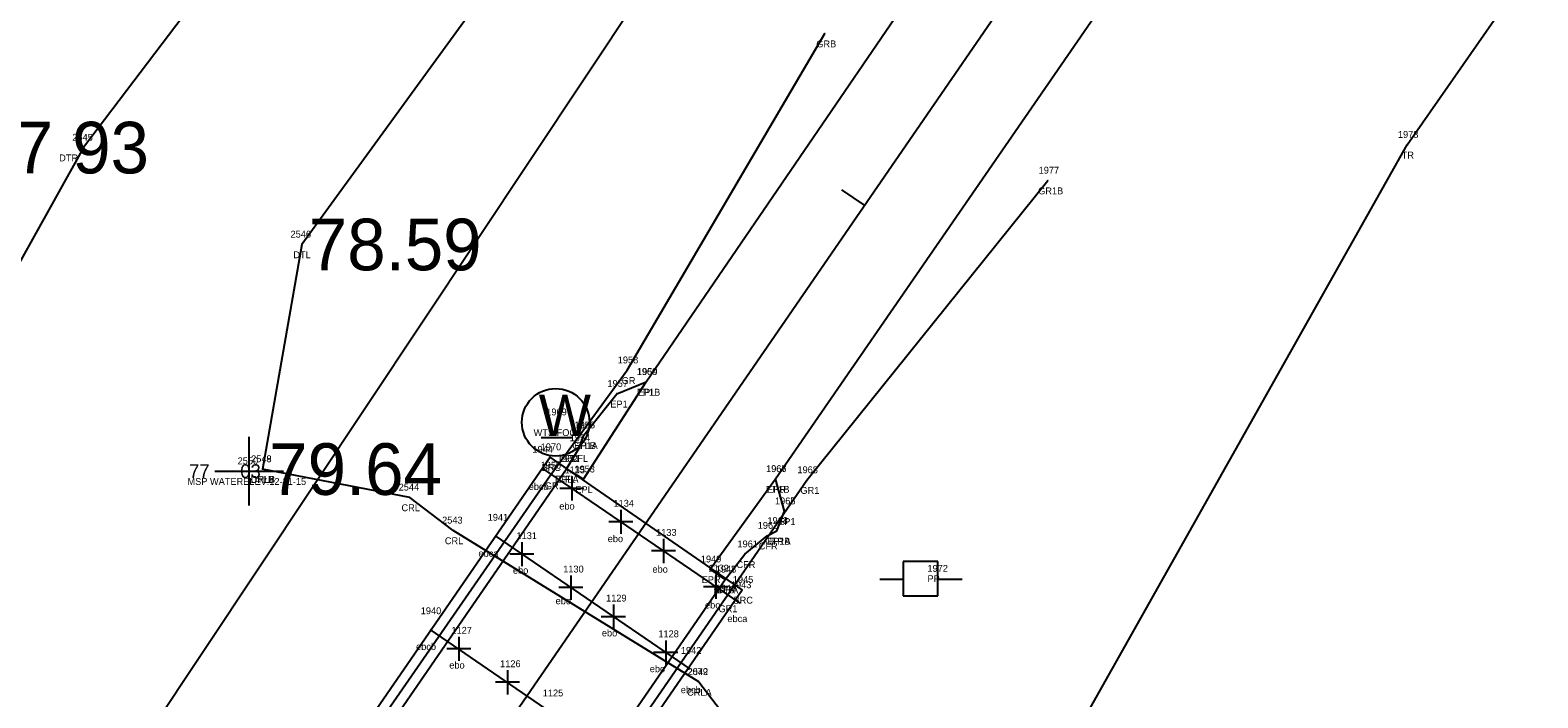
# Model space of a CAD drawing. Extents: x 2266664 to 2272542, y 716533 to 724777.
# Drawn here: x 2269953.4 to 2270172.5, y 721369.4 to 721466.4 of the extents above; entities that cross this region are included whole.
import ezdxf

# ---------------------------------------------------------------- set-up
doc = ezdxf.new("R2010")
doc.units = 0
for name, color, linetype in [('RD_EX_Bridge', 7, 'Continuous'), ('RD_EX_Bridge_txCode', 7, 'Continuous'), ('RD_EX_Conc', 7, 'Continuous'), ('RD_EX_Conc_txCode', 7, 'Continuous'), ('RD_EX_DR_Inlet_txCode', 7, 'Continuous'), ('RD_EX_GuardRail', 7, 'Continuous'), ('RD_EX_GuardRail_txCode', 7, 'Continuous'), ('RD_EX_H2O', 7, 'Continuous'), ('RD_EX_H2O_txCode', 7, 'Continuous'), ('RD_EX_Misc', 7, 'Continuous'), ('RD_EX_Misc_txCode', 7, 'Continuous'), ('RD_EX_Road', 7, 'Continuous'), ('RD_EX_Road_txCode', 7, 'Continuous'), ('RD_EX_UT', 7, 'Continuous'), ('RD_EX_UT_txCode', 7, 'Continuous'), ('RD_EX_VEG', 7, 'Continuous'), ('RD_EX_VEG_txCode', 7, 'Continuous'), ('RD_HC_Cl', 7, 'Continuous'), ('RD_HC_Data_Tic', 7, 'Continuous'), ('RD_SMD_Locator', 7, 'Continuous')]:
    doc.layers.add(name, color=color, linetype=linetype)

msp = doc.modelspace()

# ---------------------------------------------------------------- linework, layer by layer
at = {"layer": 'RD_EX_Bridge'}
msp.add_lwpolyline([(2269960.85, 721305.41), (2269988.95, 721286.47), (2270056.9, 721385.08), (2270029.02, 721404.36), (2269960.85, 721305.41)], dxfattribs=at)
at = {"layer": 'RD_EX_Conc'}
for points in [[(2269963.38, 721303.82), (2269997.07, 721352.85), (2270031.4, 721402.66), (2270033.2, 721405.68), (2270033.91, 721407.54)], [(2269983.54, 721282.33), (2269984.17, 721283.64), (2269986.54, 721288.04), (2270020.48, 721337.28), (2270054.42, 721386.58), (2270057.31, 721390.25), (2270060.54, 721392.95), (2270061.95, 721393.64)]]:
    msp.add_lwpolyline(points, dxfattribs=at)
at = {"layer": 'RD_EX_GuardRail'}
for points in [[(2269870.57, 721186.54), (2269949.59, 721286.31), (2269962.16, 721304.4), (2269963.29, 721306.38), (2269995.7, 721353.55), (2270029.01, 721401.69), (2270040.18, 721416.99), (2270068.93, 721465.92)], [(2269974.73, 721236.37), (2269968.22, 721240.45), (2269964.64, 721248.3), (2269966.87, 721257.97), (2269988.88, 721288.81), (2270021.75, 721336.4), (2270054.42, 721383.83), (2270066.31, 721401.03), (2270101.34, 721444.56)]]:
    msp.add_lwpolyline(points, dxfattribs=at)
at = {"layer": 'RD_EX_H2O'}
for points in [[(2271033.41, 722941.96), (2271017.26, 722923.37), (2271000.84, 722915.61), (2270984.69, 722924.7), (2270953.1, 722884.21), (2270916.86, 722756.99), (2270859.77, 722671.98), (2270798.36, 722591.12), (2270738.02, 722501.89), (2270682.59, 722424.89), (2270629.35, 722346.56), (2270572.53, 722262.27), (2270515.87, 722180.88), (2270459.66, 722106.47), (2270403.98, 722020.3), (2270343.58, 721932.89), (2270284.34, 721846.17), (2270230.48, 721766.75), (2270175.19, 721692.18), (2270115.51, 721607.69), (2270056.41, 721522.72), (2269992.94, 721435.27), (2269987.18, 721402.63)], [(2270599.29, 722364.14), (2270544.36, 722283.47), (2270486.41, 722202.72), (2270437.65, 722128.66), (2270381.61, 722049.14), (2270312.65, 721946.45), (2270267.02, 721881.66), (2270199.49, 721783.94), (2270145.55, 721706.24), (2270092.32, 721634.06), (2270029.51, 721539.41), (2269961.2, 721449.35), (2269937.69, 721407.23), (2269942.44, 721394.39), (2269941.06, 721353.93), (2269922.62, 721344.96)], [(2270050.62, 721371.69), (2270014.93, 721393.71), (2270008.62, 721398.51), (2269987.18, 721402.63)], [(2270050.62, 721371.69), (2270058.64, 721361.22), (2270067.88, 721340.59), (2270071.72, 721335.84), (2270077.18, 721322.68), (2270100.02, 721315.03), (2270109.33, 721309.47), (2270127.84, 721291.83), (2270185.1, 721310.38), (2270243.87, 721304.44), (2270281.75, 721346.08), (2270379.45, 721379), (2270436.63, 721386.23), (2270462.17, 721399.02)]]:
    msp.add_lwpolyline(points, dxfattribs=at)
at = {"layer": 'RD_EX_Misc'}
for p, q in [((2269985.26, 721397.33), (2269985.26, 721407.33)), ((2269980.26, 721402.33), (2269990.26, 721402.33)), ((2270056.61, 721383.12), (2270027.78, 721402.8)), ((2270032.17, 721401.56), (2270032.17, 721398.06)), ((2270033.92, 721399.81), (2270030.42, 721399.81)), ((2270039.27, 721396.71), (2270039.27, 721393.21)), ((2270041.02, 721394.96), (2270037.52, 721394.96)), ((2270020.99, 721392.92), (2270049.34, 721373.57)), ((2270024.89, 721392), (2270024.89, 721388.5)), ((2270045.46, 721392.48), (2270045.46, 721388.98)), ((2270026.64, 721390.25), (2270023.14, 721390.25)), ((2270047.21, 721390.73), (2270043.71, 721390.73)), ((2270032, 721387.15), (2270032, 721383.65)), ((2270053.06, 721387.29), (2270053.06, 721383.79)), ((2270033.75, 721385.4), (2270030.25, 721385.4)), ((2270054.81, 721385.54), (2270051.31, 721385.54)), ((2270038.19, 721382.93), (2270038.19, 721379.43)), ((2270039.94, 721381.18), (2270036.44, 721381.18)), ((2270040.13, 721359.75), (2270011.59, 721379.34)), ((2270015.72, 721378.25), (2270015.72, 721374.75)), ((2270017.47, 721376.5), (2270013.97, 721376.5)), ((2270047.54, 721375.99), (2270044.04, 721375.99)), ((2270045.79, 721377.74), (2270045.79, 721374.24)), ((2270024.56, 721371.64), (2270021.06, 721371.64)), ((2270022.81, 721373.39), (2270022.81, 721369.89))]:
    msp.add_line(p, q, dxfattribs=at)
at = {"layer": 'RD_EX_Road'}
for points in [[(2270031.4, 721402.66), (2270033.87, 721401.14), (2270042.98, 721415.3), (2270092.2, 721487.45), (2270150.09, 721571.44), (2270208.05, 721655.62), (2270267.22, 721742.06), (2270325.8, 721826.88), (2270384.21, 721912), (2270439.48, 721992.72), (2270498.7, 722078.55)], [(2270054.42, 721386.58), (2270052.25, 721388.06), (2270061.76, 721401.19), (2270112.33, 721474.56), (2270169.63, 721557.76), (2270228.06, 721642.37), (2270287.52, 721728.67), (2270345.88, 721813.8), (2270404.16, 721898.12), (2270459.42, 721978.97), (2270518.64, 722064.54)], [(2270033.91, 721407.54), (2270038.67, 721413.57), (2270042.98, 721415.3)], [(2270061.95, 721393.64), (2270063.05, 721396.5), (2270061.76, 721401.19)]]:
    msp.add_lwpolyline(points, dxfattribs=at)
at = {"layer": 'RD_EX_UT'}
for p, q in [((2270027.68, 721407.22), (2270032.31, 721407.22)), ((2270085.32, 721389.21), (2270080.32, 721389.21)), ((2270080.32, 721389.21), (2270080.32, 721384.21)), ((2270085.32, 721384.21), (2270085.32, 721389.21)), ((2270076.89, 721386.65), (2270080.36, 721386.65)), ((2270085.25, 721386.65), (2270088.89, 721386.65)), ((2270080.32, 721384.21), (2270085.32, 721384.21))]:
    msp.add_line(p, q, dxfattribs=at)
msp.add_circle((2270029.81, 721409.43), 4.91, dxfattribs=at)
at = {"layer": 'RD_EX_VEG'}
for points in [[(2268819.78, 719716.8), (2268871.54, 719776.21), (2269193.85, 720224.65), (2269408.57, 720538.5), (2269589.67, 720791.77), (2270047.56, 721479.8), (2270363.13, 721951.09), (2270746.65, 722498.38), (2270919.94, 722752.82), (2271017.26, 722923.37)], [(2269982.26, 721145.34), (2270153.55, 721449.76), (2270271.14, 721618.55), (2270388.14, 721782.77), (2270502.37, 721950.48), (2270556.28, 722038.41)]]:
    msp.add_lwpolyline(points, dxfattribs=at)
at = {"layer": 'RD_HC_Cl'}
msp.add_line((2267342.91, 717471.2), (2272360.46, 724762.59), dxfattribs=at)
at = {"layer": 'RD_HC_Data_Tic'}
msp.add_line((2270074.69, 721440.97), (2270071.4, 721443.23), dxfattribs=at)
at = {"layer": 'RD_SMD_Locator'}
for centre in [(2270068.93, 721465.92), (2269961.2, 721449.35), (2270153.55, 721449.76), (2270101.34, 721444.56), (2269992.94, 721435.27), (2270040.18, 721416.99), (2270038.67, 721413.57), (2270042.98, 721415.3), (2270042.98, 721415.3), (2270033.91, 721407.54), (2270033.91, 721407.54), (2270033.2, 721405.68), (2269987.18, 721402.63), (2269987.18, 721402.63), (2270029.02, 721404.36), (2270031.4, 721402.66), (2270031.4, 721402.66), (2270029.01, 721401.69), (2270033.87, 721401.14), (2270061.76, 721401.19), (2270061.76, 721401.19), (2270066.31, 721401.03), (2270008.62, 721398.51), (2270063.05, 721396.5), (2270014.93, 721393.71), (2270061.95, 721393.64), (2270061.95, 721393.64), (2270060.54, 721392.95), (2270057.31, 721390.25), (2270052.25, 721388.06), (2270054.42, 721386.58), (2270054.42, 721386.58), (2270056.9, 721385.08), (2270054.42, 721383.83), (2270050.62, 721371.69), (2270050.62, 721371.69)]:
    msp.add_circle(centre, 0.001, dxfattribs=at)

# ---------------------------------------------------------------- texts
at = {"layer": 'RD_EX_Bridge_txCode'}
for s, p in [('1970', (2270027.63, 721405.36)), ('BRC', (2270027.76, 721402.36)), ('1945', (2270055.55, 721386.08)), ('BRC', (2270055.65, 721383.08))]:
    msp.add_text(s, height=1, dxfattribs=at).set_placement(p)
at = {"layer": 'RD_EX_Conc_txCode'}
for s, p in [('1955', (2270032.56, 721408.54)), ('1954', (2270031.85, 721406.68)), ('1951', (2270030.34, 721403.66)), ('CFL', (2270031.99, 721403.68)), ('CFLB', (2270032.23, 721405.54)), ('CFL', (2270030.2, 721400.66)), ('1963', (2270060.58, 721394.64)), ('1962', (2270059.17, 721393.95)), ('1961', (2270056.22, 721391.25)), ('CFR', (2270059.32, 721390.95)), ('CFRB', (2270060.25, 721391.64)), ('CFR', (2270056.08, 721388.25)), ('1947', (2270053.07, 721387.58)), ('CFR', (2270053.19, 721384.58))]:
    msp.add_text(s, height=1, dxfattribs=at).set_placement(p)
at = {"layer": 'RD_EX_DR_Inlet_txCode'}
for s, p in [('77 93', (2269945.61, 721445.6)), ('78.59', (2269993.94, 721431.52)), ('79.64', (2269988.18, 721398.88))]:
    msp.add_text(s, height=7.5, dxfattribs=at).set_placement(p)
at = {"layer": 'RD_EX_GuardRail_txCode'}
for s, p in [('GRB', (2270067.68, 721463.92)), ('1977', (2270099.99, 721445.56)), ('GR1B', (2270099.92, 721442.56)), ('1958', (2270038.83, 721417.99)), ('GR', (2270039.4, 721414.99)), ('1950', (2270027.62, 721402.69)), ('1968', (2270064.94, 721402.03)), ('GR', (2270028.23, 721399.69)), ('GR1', (2270065.37, 721399.03)), ('1946', (2270053.05, 721384.83)), ('GR1', (2270053.47, 721381.83))]:
    msp.add_text(s, height=1, dxfattribs=at).set_placement(p)
at = {"layer": 'RD_EX_H2O_txCode'}
for s, p in [('2545', (2269959.57, 721450.35)), ('DTR', (2269957.66, 721447.35)), ('2546', (2269991.28, 721436.27)), ('DTL', (2269991.69, 721433.27)), ('2548', (2269985.55, 721403.63)), ('2549', (2269985.55, 721403.63)), ('CRLB', (2269985.48, 721400.63)), ('DTLB', (2269985.47, 721400.63)), ('2544', (2270006.99, 721399.51)), ('CRL', (2270007.4, 721396.51)), ('2543', (2270013.3, 721394.71)), ('CRL', (2270013.7, 721391.71)), ('2079', (2270048.95, 721372.69)), ('2542', (2270048.99, 721372.69)), ('CRLA', (2270048.9, 721369.69)), ('CRLA', (2270048.9, 721369.69))]:
    msp.add_text(s, height=1, dxfattribs=at).set_placement(p)
at = {"layer": 'RD_EX_Misc_txCode'}
for s, height, p in [('1944', 1, (2270026.43, 721405)), ('77      03', 2, (2269976.54, 721401.33)), ('2550', 1, (2269983.59, 721403.33)), ('1135', 1, (2270031.1, 721402.01)), ('MSP WATERELEV.12-21-15', 1, (2269976.3, 721400.33)), ('ebcb', 1, (2270025.89, 721399.59)), ('1134', 1, (2270038.21, 721397.16)), ('1941', 1, (2270019.93, 721395.12)), ('ebo', 1, (2270030.33, 721396.75)), ('1131', 1, (2270024.11, 721392.45)), ('1133', 1, (2270044.4, 721392.93)), ('ebo', 1, (2270037.37, 721392.01)), ('ebca', 1, (2270018.59, 721389.88)), ('ebo', 1, (2270023.6, 721387.42)), ('1130', 1, (2270030.9, 721387.6)), ('ebo', 1, (2270043.87, 721387.57)), ('1132', 1, (2270052, 721387.74)), ('1943', 1, (2270055.27, 721385.32)), ('1940', 1, (2270010.2, 721381.54)), ('ebo', 1, (2270029.8, 721382.98)), ('1129', 1, (2270037.13, 721383.38)), ('ebo', 1, (2270051.51, 721382.37)), ('ebca', 1, (2270054.76, 721380.39)), ('1127', 1, (2270014.66, 721378.7)), ('ebo', 1, (2270036.52, 721378.31)), ('1128', 1, (2270044.73, 721378.19)), ('ebcb', 1, (2270009.52, 721376.33)), ('1942', 1, (2270048, 721375.77)), ('ebo', 1, (2270014.35, 721373.64)), ('1126', 1, (2270021.73, 721373.84)), ('ebo', 1, (2270043.48, 721373.11)), ('1125', 1, (2270027.93, 721369.59)), ('ebcb', 1, (2270047.99, 721370.06))]:
    msp.add_text(s, height=height, dxfattribs=at).set_placement(p)
at = {"layer": 'RD_EX_Road_txCode'}
for s, p in [('1957', (2270037.33, 721414.57)), ('1960', (2270041.57, 721416.3)), ('1959', (2270041.64, 721416.3)), ('EP1B', (2270041.59, 721413.3)), ('EPL', (2270041.78, 721413.3)), ('EP1', (2270037.75, 721411.57)), ('1956', (2270032.54, 721408.54)), ('1952', (2270030.06, 721403.66)), ('EP1A', (2270032.5, 721405.54)), ('1953', (2270032.53, 721402.14)), ('1966', (2270060.37, 721402.19)), ('1967', (2270060.39, 721402.19)), ('EPLA', (2270029.71, 721400.66)), ('EPL', (2270032.67, 721399.14)), ('EP1B', (2270060.37, 721399.19)), ('EPR', (2270060.53, 721399.19)), ('1965', (2270061.68, 721397.5)), ('1964', (2270060.58, 721394.64)), ('EP1', (2270062.13, 721394.5)), ('EP1A', (2270060.54, 721391.64)), ('1949', (2270050.9, 721389.06)), ('EPR', (2270051.02, 721386.06)), ('1948', (2270053.07, 721387.58)), ('EPRA', (2270052.7, 721384.58))]:
    msp.add_text(s, height=1, dxfattribs=at).set_placement(p)
at = {"layer": 'RD_EX_UT'}
msp.add_text('W', height=6, dxfattribs=at).set_placement((2270027.35, 721407.42))
at = {"layer": 'RD_EX_UT_txCode'}
for s, p in [('1969', (2270028.44, 721410.43)), ('WTS FOC', (2270026.6, 721407.43)), ('1972', (2270083.83, 721387.7)), ('PP', (2270083.83, 721386.2))]:
    msp.add_text(s, height=1, dxfattribs=at).set_placement(p)
at = {"layer": 'RD_EX_VEG_txCode'}
for s, p in [('1978', (2270152.2, 721450.76)), ('TR', (2270152.75, 721447.76))]:
    msp.add_text(s, height=1, dxfattribs=at).set_placement(p)

doc.saveas('drawing.dxf')
